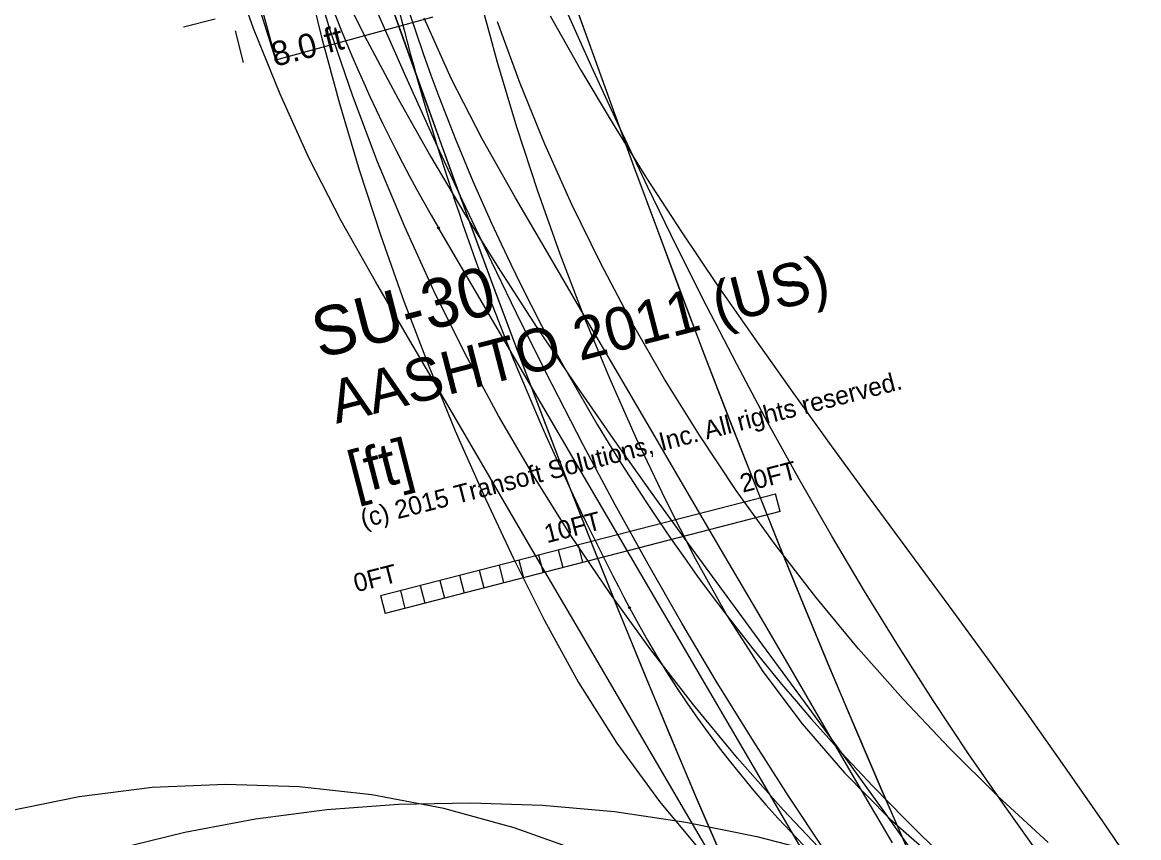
# Model space of a CAD drawing. Extents: x 916040 to 917457, y 328936 to 330267.
# Drawn here: x 916654.5 to 916709.3, y 329738.6 to 329778.6 of the extents above; entities that cross this region are included whole.
import ezdxf

# ---------------------------------------------------------------- set-up
doc = ezdxf.new("R2010")
doc.units = 0
for name, color, linetype in [('EB_LeftontoManchester_WB67', 7, 'Continuous'), ('EB_LeftontoManchester_WB67_v2', 7, 'Continuous'), ('NB_LeftontoRoute25_WB67', 7, 'Continuous'), ('NB_ThruontoManchester_WB67', 7, 'Continuous'), ('SU_IntoDriveway', 7, 'Continuous'), ('SU_IntoDriveway_Rt', 7, 'Continuous'), ('WB_LeftontoSaco_WB67', 7, 'Continuous'), ('WB_RightontoManchester_WB67', 7, 'Continuous')]:
    doc.layers.add(name, color=color, linetype=linetype)

msp = doc.modelspace()

# ---------------------------------------------------------------- linework, layer by layer
at = {"layer": 'EB_LeftontoManchester_WB67'}
for points in [[(916694.14, 329737.518), (916691.828, 329739.96), (916689.588, 329742.489), (916687.423, 329745.103), (916685.338, 329747.795), (916683.337, 329750.564), (916681.423, 329753.403), (916679.6, 329756.31), (916677.87, 329759.28), (916676.237, 329762.311), (916674.703, 329765.397), (916673.271, 329768.536), (916671.942, 329771.723), (916670.718, 329774.955), (916669.601, 329778.228), (916668.593, 329781.538)], [(916688.896, 329737.482), (916687.575, 329740.55), (916686.272, 329743.631), (916684.989, 329746.722), (916683.727, 329749.823), (916682.483, 329752.934), (916681.26, 329756.051), (916680.054, 329759.176), (916678.865, 329762.306), (916677.691, 329765.442), (916676.531, 329768.58), (916675.383, 329771.722), (916674.245, 329774.865), (916673.116, 329778.01), (916671.993, 329781.154)], [(916698.009, 329737.861), (916696.691, 329740.87), (916695.392, 329743.889), (916694.111, 329746.918), (916692.85, 329749.956), (916691.608, 329753.006), (916690.385, 329756.066), (916689.18, 329759.136), (916687.992, 329762.217), (916686.818, 329765.307), (916685.658, 329768.406), (916684.509, 329771.513), (916683.371, 329774.628), (916682.241, 329777.749), (916681.118, 329780.876)], [(916704.823, 329738.351), (916702.359, 329740.634), (916699.987, 329742.978), (916697.708, 329745.385), (916695.522, 329747.853), (916693.43, 329750.382), (916691.432, 329752.971), (916689.529, 329755.618), (916687.721, 329758.321), (916686.01, 329761.077), (916684.396, 329763.885), (916682.88, 329766.741), (916681.464, 329769.643), (916680.147, 329772.588), (916678.932, 329775.573), (916677.819, 329778.595)]]:
    msp.add_lwpolyline(points, dxfattribs=at)
msp.add_arc((916768.512, 329810.214), 100, 192.26429, 233.38938, dxfattribs=at)
at = {"layer": 'EB_LeftontoManchester_WB67_v2'}
for points in [[(916694.14, 329737.518), (916691.828, 329739.96), (916689.588, 329742.489), (916687.423, 329745.103), (916685.338, 329747.795), (916683.337, 329750.564), (916681.423, 329753.403), (916679.6, 329756.31), (916677.87, 329759.28), (916676.237, 329762.311), (916674.703, 329765.397), (916673.271, 329768.536), (916671.942, 329771.723), (916670.718, 329774.955), (916669.601, 329778.228), (916668.593, 329781.538)], [(916688.903, 329737.472), (916687.583, 329740.536), (916686.282, 329743.613), (916685, 329746.701), (916683.739, 329749.799), (916682.497, 329752.905), (916681.274, 329756.019), (916680.069, 329759.14), (916678.881, 329762.267), (916677.709, 329765.398), (916676.55, 329768.534), (916675.403, 329771.671), (916674.266, 329774.811), (916673.137, 329777.952), (916672.016, 329781.093)], [(916698.014, 329737.855), (916696.698, 329740.861), (916695.4, 329743.876), (916694.12, 329746.901), (916692.861, 329749.936), (916691.62, 329752.982), (916690.398, 329756.038), (916689.194, 329759.105), (916688.007, 329762.181), (916686.834, 329765.268), (916685.675, 329768.363), (916684.528, 329771.467), (916683.39, 329774.578), (916682.262, 329777.695), (916681.14, 329780.819)], [(916704.823, 329738.351), (916702.359, 329740.634), (916699.987, 329742.978), (916697.708, 329745.385), (916695.522, 329747.853), (916693.43, 329750.382), (916691.432, 329752.971), (916689.529, 329755.618), (916687.721, 329758.321), (916686.01, 329761.077), (916684.396, 329763.885), (916682.88, 329766.741), (916681.464, 329769.643), (916680.147, 329772.588), (916678.932, 329775.573), (916677.819, 329778.595)]]:
    msp.add_lwpolyline(points, dxfattribs=at)
msp.add_arc((916768.512, 329810.214), 100, 192.26429, 233.38938, dxfattribs=at)
at = {"layer": 'NB_LeftontoRoute25_WB67'}
msp.add_lwpolyline([(916659.079, 329738.022), (916662.491, 329738.858), (916665.95, 329739.507), (916669.445, 329739.966), (916672.964, 329740.233), (916676.496, 329740.307), (916680.03, 329740.185), (916683.554, 329739.869), (916687.058, 329739.358), (916690.53, 329738.654), (916693.96, 329737.759)], dxfattribs=at)
at = {"layer": 'NB_ThruontoManchester_WB67'}
for points in [[(916668.391, 329781.119), (916669.189, 329777.848), (916670.072, 329774.586), (916671.04, 329771.337), (916672.093, 329768.105), (916673.229, 329764.893), (916674.447, 329761.704), (916675.747, 329758.542), (916677.128, 329755.41), (916678.588, 329752.309), (916680.128, 329749.243), (916681.797, 329746.192), (916683.677, 329743.221), (916685.758, 329740.365), (916688.029, 329737.641)], [(916670, 329780.514), (916671.433, 329777.661), (916672.951, 329774.811), (916674.549, 329771.976), (916676.221, 329769.162), (916677.959, 329766.372), (916679.754, 329763.609), (916681.597, 329760.872), (916683.478, 329758.16), (916685.387, 329755.473), (916687.313, 329752.808), (916689.245, 329750.165), (916691.175, 329747.541), (916693.091, 329744.933), (916694.985, 329742.338), (916696.85, 329739.756), (916698.676, 329737.182)], [(916676.943, 329779.815), (916677.81, 329776.614), (916678.756, 329773.447), (916679.779, 329770.315), (916680.88, 329767.216), (916682.057, 329764.153), (916683.311, 329761.127), (916684.64, 329758.137), (916686.043, 329755.187), (916687.52, 329752.275), (916689.091, 329749.439), (916690.835, 329746.737), (916692.752, 329744.177), (916694.832, 329741.766), (916697.067, 329739.514), (916699.445, 329737.428)], [(916680.41, 329778.888), (916681.91, 329776.227), (916683.486, 329773.575), (916685.133, 329770.931), (916686.845, 329768.295), (916688.616, 329765.666), (916690.436, 329763.043), (916692.296, 329760.424), (916694.187, 329757.808), (916696.099, 329755.193), (916698.021, 329752.578), (916699.945, 329749.96), (916701.86, 329747.337), (916703.758, 329744.708), (916705.629, 329742.071), (916707.467, 329739.424), (916709.262, 329736.765)]]:
    msp.add_lwpolyline(points, dxfattribs=at)
msp.add_circle((916684.292, 329749.868), 0.0417, dxfattribs=at)
msp.add_circle((916684.292, 329749.868), 0.0417, dxfattribs=at)
for centre, radius, start, end in [((916800.902, 329811.725), 132, 191.6689, 207.94419), ((916728.463, 329773.299), 50, 207.9442, 241.1365)]:
    msp.add_arc(centre, radius, start, end, dxfattribs=at)
at = {"layer": 'SU_IntoDriveway'}
for p, q in [((916663.972, 329778.728), (916662.423, 329778.328)), ((916664.947, 329778.153), (916665.346, 329776.603)), ((916672.087, 329750.458), (916691.453, 329755.451)), ((916691.678, 329754.58), (916691.453, 329755.451)), ((916691.678, 329754.58), (916672.311, 329749.587)), ((916680.802, 329752.705), (916681.026, 329751.834)), ((916681.77, 329752.955), (916681.995, 329752.083)), ((916678.865, 329752.206), (916679.09, 329751.334)), ((916679.833, 329752.456), (916680.058, 329751.584)), ((916676.928, 329751.707), (916677.153, 329750.835)), ((916677.897, 329751.956), (916678.121, 329751.085)), ((916674.023, 329750.958), (916674.248, 329750.086)), ((916674.992, 329751.207), (916675.216, 329750.336)), ((916675.96, 329751.457), (916676.185, 329750.585)), ((916672.087, 329750.458), (916672.311, 329749.587)), ((916673.055, 329750.708), (916673.28, 329749.836))]:
    msp.add_line(p, q, dxfattribs=at)
at = {"layer": 'SU_IntoDriveway_Rt'}
for p, q in [((916659.074, 329805.681), (916666.953, 329776.734)), ((916666.953, 329776.734), (916674.672, 329778.835))]:
    msp.add_line(p, q, dxfattribs=at)
msp.add_lwpolyline([(916666.953, 329776.734), (916665.944, 329779.917), (916664.801, 329783.092), (916663.977, 329786.352), (916663.451, 329789.6), (916662.576, 329792.816), (916661.7, 329796.032), (916660.825, 329799.249), (916659.95, 329802.465), (916659.074, 329805.681), (916659.074, 329805.681), (916658.946, 329806.345)], dxfattribs=at)
msp.add_circle((916666.953, 329776.734), 0.0417, dxfattribs=at)
at = {"layer": 'WB_LeftontoSaco_WB67'}
msp.add_lwpolyline([(916681.983, 329737.873), (916678.63, 329739.073), (916675.182, 329740.014), (916671.662, 329740.687), (916668.091, 329741.086), (916664.494, 329741.206), (916660.892, 329741.044), (916657.31, 329740.6), (916653.769, 329739.876), (916650.301, 329738.882), (916646.922, 329737.696)], dxfattribs=at)
at = {"layer": 'WB_RightontoManchester_WB67'}
msp.add_line((916701.8, 329722.539), (916674.926, 329768.491), dxfattribs=at)
for points in [[(916688.819, 329736.824), (916687.112, 329739.74), (916685.407, 329742.652), (916683.705, 329745.561), (916682.005, 329748.467), (916680.306, 329751.37), (916678.609, 329754.272), (916676.913, 329757.172), (916675.218, 329760.07), (916673.523, 329762.967), (916671.83, 329765.863), (916670.15, 329768.831), (916668.587, 329771.898), (916667.154, 329775.046), (916665.856, 329778.266), (916664.698, 329781.552)], [(916693.895, 329737.924), (916692.07, 329740.666), (916690.288, 329743.446), (916688.55, 329746.262), (916686.857, 329749.114), (916685.206, 329751.997), (916683.596, 329754.91), (916682.027, 329757.85), (916680.495, 329760.815), (916678.999, 329763.802), (916677.537, 329766.809), (916676.105, 329769.832), (916674.701, 329772.871), (916673.323, 329775.921), (916671.967, 329778.983)], [(916704.533, 329737.574), (916702.709, 329740.121), (916700.925, 329742.702), (916699.182, 329745.321), (916697.48, 329747.977), (916695.818, 329750.67), (916694.196, 329753.401), (916692.612, 329756.168), (916691.064, 329758.971), (916689.55, 329761.806), (916688.07, 329764.672), (916686.62, 329767.568), (916685.198, 329770.49), (916683.803, 329773.436), (916682.431, 329776.405), (916681.081, 329779.393)], [(916697.182, 329738.341), (916695.512, 329741.201), (916693.839, 329744.065), (916692.164, 329746.933), (916690.486, 329749.804), (916688.805, 329752.679), (916687.124, 329755.555), (916685.44, 329758.434), (916683.756, 329761.315), (916682.071, 329764.196), (916680.385, 329767.08), (916678.698, 329769.964), (916677.064, 329772.853), (916675.571, 329775.79), (916674.221, 329778.778)]]:
    msp.add_lwpolyline(points, dxfattribs=at)
msp.add_circle((916674.926, 329768.491), 0.0417, dxfattribs=at)
msp.add_circle((916674.926, 329768.491), 0.0417, dxfattribs=at)
msp.add_arc((916739.667, 329806.353), 75, 192.55823, 210.31996, dxfattribs=at)

# ---------------------------------------------------------------- texts
at = {"layer": 'SU_IntoDriveway'}
for s, height, p in [('8.0 ft', 1.2, (916666.907, 329776.386)), ('AASHTO 2011 (US)', 2.1, (916669.915, 329758.883)), ('SU-30', 2.4, (916669.091, 329762.078)), ('(c) 2015 Transoft Solutions, Inc. All rights reserved.', 0.9, (916671.233, 329753.77)), ('[ft]', 2.1, (916670.813, 329755.397)), ('20FT', 0.9, (916689.847, 329755.502)), ('10FT', 0.9, (916680.247, 329753.027)), ('0FT', 0.9, (916670.895, 329750.616))]:
    msp.add_text(s, height=height, rotation=14.4569, dxfattribs=at).set_placement(p)

doc.saveas('drawing.dxf')
